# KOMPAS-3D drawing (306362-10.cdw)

Referenced files in C:\Documents and Settings\Icedog\Рабочий стол\тау\рисунки\: котел2.jpg, кривая разгона.JPG, расчетная и заданная кривые разгона.JPG, расчетная и смоделированные кривые разгона.JPG, ачх.JPG, фчх.JPG
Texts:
  КП 220301.072676.2011
  Расчет системы  автоматического регулирования температуры нагревательной печи
  Григорьев А.А.
  Текст на чертеже
  Размерные надписи
  Шероховатость
  Линия-выноска #1
  Линия-выноска #2
  Линия-выноска #3
  Отклонения формы и база
  Заголовок таблицы
  Ячейка таблицы
  Стрелка вида
  Обозначение изменения
  Фигурная скобка
  Номер узла
  Марка координационной оси
  VRCB
  Выносная надпись
  Обозначение узла
  Марка/позиционное обозначение с линией-выноской
  Марка/позиционное обозначение на линии
  Марка/позиционное обозначение без линии-выноски
  Переходные характеристики объекта
  Амплитудно-частотная
  характеристика объекта (АЧХ)
  Фазо-частотная
  характеристика объекта (ФЧХ)
  рисунки\котел2.jpg
  рисунки\кривая разгона.JPG
  рисунки\расчетная и заданная кривые разгона.JPG
  рисунки\расчетная и смоделированные кривые разгона.JPG
  рисунки\ачх.JPG
  рисунки\фчх.JPG
  Расчетная и смоделированная кривые разгона
  Расчетная и заданная кривые разгона
  Расчет системы
  автоматического регулирования
  температуры нагревательной печи
  Кокуев А.Г.
  Переходные и частотные
  характеристики объекта.
  Выбор параметров регулятора
  АГТУ ДИА-41
  КП 220301.072676.2011-
Dimensions and other numbers on the sheet: 7; 1:1; 1; 0; 2; 3; 4; 5; 6; 8; 9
